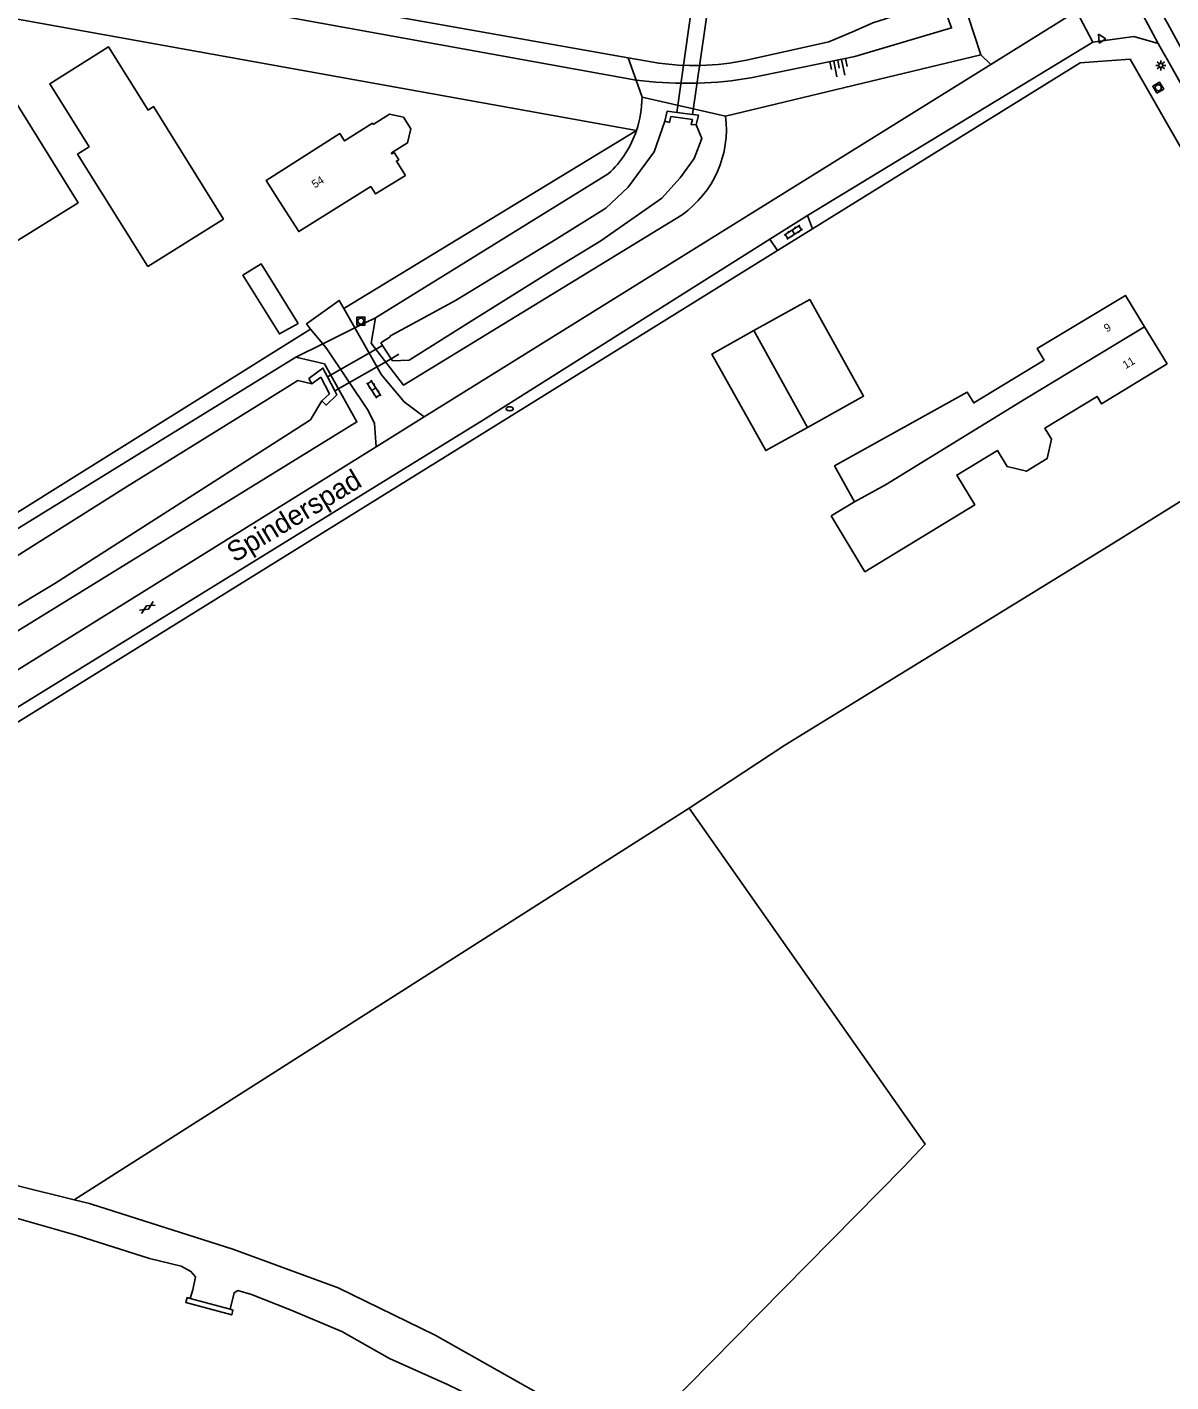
# Model space of a CAD drawing. Extents: x 133000 to 136000, y 400500 to 403500.
# Drawn here: x 133301.9 to 133444.8, y 401055.6 to 401224.9 of the extents above; entities that cross this region are included whole.
import ezdxf

# ---------------------------------------------------------------- set-up
doc = ezdxf.new("R2010")
doc.units = 0
for name, color, linetype in [('gg-afsc-draadraster', 7, 'Continuous'), ('gg-afsc-hekwerk', 7, 'Continuous'), ('gg-afsc-muur', 7, 'Continuous'), ('gg-anno-huisnummerreeks BGT', 7, 'Continuous'), ('gg-anno-openbare ruimte label', 7, 'Continuous'), ('gg-bbg-bijgebouw', 7, 'Continuous'), ('gg-bbg-hoofdgebouw', 7, 'Continuous'), ('gg-bbg-open loods', 7, 'Continuous'), ('gg-bbg-tussenscheiding', 7, 'Continuous'), ('gg-knt-BGT kruinlijn', 7, 'Continuous'), ('gg-knt-bovenkant onderkant talud', 7, 'Continuous'), ('gg-knt-verharding', 7, 'Continuous'), ('gg-kntw-bovenkant insteek waterloop', 7, 'Continuous'), ('gg-kntw-waterlijn', 7, 'Continuous'), ('gg-kwrk-duiker nz vlak', 7, 'Continuous'), ('gg-kwrk-faunavoorziening', 7, 'Continuous'), ('gg-kwrk-uitstroombak niveau min 01', 7, 'Continuous'), ('gt-grn-groengrens', 7, 'Continuous'), ('gt-grn-vlakafsluiter', 7, 'Continuous'), ('gt-symb-brandkraan', 7, 'Continuous'), ('gt-symb-gesloten verharding', 7, 'Continuous'), ('gt-symb-klinker verharding', 7, 'Continuous'), ('gt-symb-lichtmast', 7, 'Continuous'), ('gt-symb-rioolschacht', 7, 'Continuous'), ('gt-symb-talud symbool', 7, 'Continuous'), ('gt-symb-waterafsluiter', 7, 'Continuous'), ('gx-grn-maaiveld', 7, 'Continuous')]:
    doc.layers.add(name, color=color, linetype=linetype)

# ---------------------------------------------------------------- blocks, each defined once
blk = doc.blocks.new('gt0-RS')
at = {"layer": 'gt-symb-rioolschacht'}
blk.add_lwpolyline([(-0.5, -0.5), (0.5, -0.5), (0.5, 0.5), (-0.5, 0.5)], close=True, dxfattribs=at)
blk.add_circle((0, 0), 0.375, dxfattribs=at)
blk = doc.blocks.new('gt0-LMAST')
at = {"layer": 'gt-symb-lichtmast'}
for p, q in [((-0.18, 0.17), (-0.45, 0.44)), ((-0.01, 0.25), (-0.01, 0.62)), ((0.17, 0.17), (0.44, 0.44)), ((-0.26, 0), (-0.63, 0)), ((-0.18, -0.18), (-0.45, -0.45)), ((-0.01, -0.25), (-0.01, -0.63)), ((0.44, -0.45), (0.17, -0.18)), ((0.24, 0), (0.62, 0))]:
    blk.add_line(p, q, dxfattribs=at)
blk.add_circle((-0.01, 0), 0.25, dxfattribs=at)
blk = doc.blocks.new('gt0-WAFSL')
at = {"layer": 'gt-symb-waterafsluiter'}
for p, q in [((-0.5, -0.33), (0, 0.67)), ((0, 0.67), (0.5, -0.33)), ((0.5, -0.33), (-0.5, -0.33))]:
    blk.add_line(p, q, dxfattribs=at)
blk = doc.blocks.new('gt0-TALUD_1')
at = {"layer": 'gt-symb-talud symbool'}
for p, q in [((-1, -1), (-1, 0)), ((0.5, -2), (0.5, 0)), ((-0.5, -2), (-0.5, 0)), ((0, -1), (0, 0)), ((1, -1), (1, 0))]:
    blk.add_line(p, q, dxfattribs=at)
blk = doc.blocks.new('gt0-KL1')
at = {"layer": 'gt-symb-klinker verharding'}
for p, q in [((-1.15, 0.3), (1.15, 0.3)), ((-1, -0.3), (-1, 0.3)), ((-0.5, 0.3), (-0.5, 0.45)), ((0, -0.3), (0, 0.3)), ((0.5, 0.3), (0.5, 0.45)), ((1, -0.3), (1, 0.3)), ((-1.15, -0.3), (1.15, -0.3)), ((-0.5, -0.45), (-0.5, -0.3)), ((0.5, -0.45), (0.5, -0.3))]:
    blk.add_line(p, q, dxfattribs=at)
blk = doc.blocks.new('gt0-BR')
at = {"layer": 'gt-symb-brandkraan'}
for centre, radius, start, end in [((-0.24, 0), 0.206, 107.5669, 252.4331), ((0.6, -2.66), 3, 106.892, 107.5669), ((0, -0.69), 0.938, 73.108, 106.892), ((-0.6, -2.66), 3, 72.4331, 73.108), ((0.24, 0), 0.206, 287.567, 72.4331), ((0.6, 2.66), 3, 252.4331, 253.108), ((0, 0.69), 0.938, 253.108, 286.8921), ((-0.6, 2.66), 3, 286.8921, 287.567)]:
    blk.add_arc(centre, radius, start, end, dxfattribs=at)
blk = doc.blocks.new('gt0-GESVH1')
at = {"layer": 'gt-symb-gesloten verharding'}
for p, q in [((-0.99, -0.26), (0.01, 0.24)), ((0.01, -0.26), (-0.99, 0.24)), ((0.01, 0.24), (1.01, -0.26)), ((1.01, 0.24), (0.01, -0.26))]:
    blk.add_line(p, q, dxfattribs=at)

msp = doc.modelspace()

# ---------------------------------------------------------------- linework, layer by layer
at = {"layer": 'gg-afsc-draadraster'}
msp.add_lwpolyline([(133465.2, 401177.6), (133436.96, 401160.03), (133396.55, 401135.16), (133384.57, 401127.31)], dxfattribs=at)
at = {"layer": 'gg-afsc-hekwerk'}
msp.add_lwpolyline([(133435.08, 401220.54), (133439.67, 401220.88), (133459.11, 401186.98)], dxfattribs=at)
at = {"layer": 'gg-afsc-muur'}
msp.add_lwpolyline([(133348.29, 401184.03), (133347.35, 401183.43), (133346.27, 401185.12), (133346.07, 401185.44), (133347.24, 401186.2)], dxfattribs=at)
at = {"layer": 'gg-bbg-bijgebouw'}
for p, q in [((133326.41, 401200.9), (133316.94, 401194.99)), ((133399.38, 401174.88), (133392.67, 401186.97))]:
    msp.add_line(p, q, dxfattribs=at)
for points in [[(133316.94, 401194.99), (133308.17, 401209.03), (133309.61, 401209.93), (133304.69, 401217.82), (133312.04, 401222.41), (133316.97, 401214.52), (133317.66, 401214.95), (133326.41, 401200.9)], [(133289.72, 401215.25), (133297.55, 401220.13), (133308.26, 401202.94), (133300.42, 401198.06), (133289.72, 401215.25)], [(133335.71, 401187.85), (133333.39, 401186.55), (133328.83, 401193.89), (133331.1, 401195.3), (133335.71, 401187.85)], [(133392.67, 401186.97), (133387.43, 401184.04), (133394.15, 401171.98), (133399.38, 401174.88)]]:
    msp.add_lwpolyline(points, dxfattribs=at)
at = {"layer": 'gg-bbg-hoofdgebouw'}
for p, q in [((133441.47, 401187.46), (133444.31, 401182.8)), ((133402.31, 401163.81), (133405.24, 401165.56)), ((133406.55, 401156.82), (133402.31, 401163.81))]:
    msp.add_line(p, q, dxfattribs=at)
for points in [[(133345.1, 401212.73), (133347.12, 401213.99), (133348.88, 401213.62), (133349.79, 401212.17), (133349.4, 401210.42), (133347.38, 401209.16), (133347.45, 401209.05), (133347.72, 401209.22), (133348.29, 401208.32), (133348.01, 401208.15), (133349.13, 401206.36)], [(133345.1, 401212.73), (133345.01, 401212.88), (133341.53, 401210.66), (133340.95, 401211.58), (133331.74, 401205.71), (133333.39, 401203.12)], [(133349.13, 401206.36), (133345.4, 401204.04), (133344.82, 401204.97), (133335.8, 401199.34), (133333.39, 401203.12)], [(133428.95, 401183.29), (133428.08, 401184.75), (133439.09, 401191.37), (133441.47, 401187.46)], [(133405.24, 401165.56), (133402.74, 401170.07), (133419.33, 401179.27), (133420.14, 401177.94), (133428.95, 401183.29)], [(133444.31, 401182.8), (133436.11, 401177.81), (133435.54, 401178.75), (133429.02, 401174.79), (133429.87, 401173.39), (133429.3, 401170.98), (133426.71, 401169.41), (133424.31, 401170.01), (133423.1, 401172.01), (133418.01, 401168.93), (133420.27, 401165.21), (133406.55, 401156.82)]]:
    msp.add_lwpolyline(points, dxfattribs=at)
at = {"layer": 'gg-bbg-open loods'}
msp.add_lwpolyline([(133392.67, 401186.97), (133399.65, 401190.85), (133406.38, 401178.79), (133399.38, 401174.88)], dxfattribs=at)
at = {"layer": 'gg-bbg-tussenscheiding'}
msp.add_lwpolyline([(133405.24, 401165.56), (133409.13, 401167.72), (133426.52, 401178.39), (133441.47, 401187.46)], dxfattribs=at)
at = {"layer": 'gg-knt-BGT kruinlijn'}
msp.add_line((133209.8, 401248.76), (133377.94, 401218.24), dxfattribs=at)
for points in [[(133392.27, 401218.55), (133405.27, 401221.21), (133417.37, 401224.79), (133415.97, 401228.6)], [(133377.94, 401218.24), (133380.41, 401217.99), (133382.89, 401217.87), (133385.7, 401217.88)]]:
    msp.add_lwpolyline(points, dxfattribs=at)
msp.add_arc((133384.08, 401266.1), 48.25, 271.9242, 279.7732, dxfattribs=at)
at = {"layer": 'gg-knt-bovenkant onderkant talud'}
for p, q in [((133376.94, 401221.05), (133209.24, 401250.82)), ((133418.48, 401229.26), (133421.02, 401221.43)), ((133421.02, 401221.43), (133389.14, 401213.77))]:
    msp.add_line(p, q, dxfattribs=at)
for points in [[(133391.73, 401220.77), (133402.02, 401223.06), (133405.19, 401224.38), (133407.51, 401225.41), (133410.8, 401226.46), (133410.48, 401227.91)], [(133386.05, 401220.1), (133384.63, 401220.08), (133383.21, 401220.14), (133380.79, 401220.37), (133376.94, 401221.05)]]:
    msp.add_lwpolyline(points, dxfattribs=at)
msp.add_arc((133385.11, 401252.15), 32.07, 271.6661, 281.9033, dxfattribs=at)
at = {"layer": 'gg-knt-verharding'}
for p, q in [((133443.2, 401222.85), (133437.58, 401233.34)), ((133422.26, 401220.21), (133432.97, 401226.87)), ((133435.02, 401223.02), (133432.97, 401226.87)), ((133399.36, 401201.35), (133435.02, 401223.02)), ((133351.46, 401176.2), (133422.26, 401220.21)), ((133399.36, 401201.35), (133394.65, 401198.38)), ((133399.36, 401201.35), (133399.98, 401199.67)), ((133394.65, 401198.38), (133395.62, 401196.96)), ((133342.82, 401187.3), (133341.43, 401189.75)), ((133337.29, 401187.16), (133338.81, 401185.31)), ((133345.47, 401172.47), (133351.46, 401176.2)), ((133345.47, 401172.47), (133248.34, 401112.04))]:
    msp.add_line(p, q, dxfattribs=at)
for points in [[(133443.2, 401222.85), (133440.15, 401223.72), (133435.02, 401223.02)], [(133249.3, 401106.19), (133249.33, 401106.49), (133249.52, 401107.17), (133249.83, 401107.81), (133250.24, 401108.38), (133250.74, 401108.88), (133253.5, 401110.84), (133358.88, 401175.83), (133394.65, 401198.38)], [(133341.43, 401189.75), (133340.86, 401190.75), (133336.76, 401187.81), (133337.29, 401187.16)], [(133351.46, 401176.2), (133348.96, 401178.06), (133346.13, 401181.45), (133342.82, 401187.3)], [(133338.81, 401185.31), (133339.33, 401184.68), (133344.49, 401177.01), (133345.28, 401175.37), (133345.47, 401172.47)]]:
    msp.add_lwpolyline(points, dxfattribs=at)
for centre, radius, start, end in [((135147.9, 402169.75), 1947.82, 208.68031, 210.16323), ((134720.52, 401936.31), 1463.07, 209.18599, 210.66988)]:
    msp.add_arc(centre, radius, start, end, dxfattribs=at)
at = {"layer": 'gg-kntw-bovenkant insteek waterloop'}
for p, q in [((133378.69, 401216.13), (133389.14, 401213.77)), ((133345.38, 401188.56), (133374.48, 401206.55)), ((133229.22, 401118.21), (133335.42, 401183.64)), ((133307.74, 401078.39), (133309.67, 401077.91))]:
    msp.add_line(p, q, dxfattribs=at)
for points in [[(133383.7, 401201.45), (133348.88, 401180.17), (133344.84, 401185.41), (133345.38, 401188.56)], [(133230.94, 401106.47), (133343.06, 401175.57), (133339.01, 401182.84), (133335.42, 401183.64)], [(133281.23, 401085.11), (133286.95, 401083.77), (133300.72, 401080.13), (133307.74, 401078.39)], [(133322.23, 401066.06), (133322.55, 401067.13), (133322.9, 401068.76), (133322.33, 401069.44), (133321.13, 401070.07), (133317.15, 401071.05), (133308.11, 401073.94), (133296.7, 401077.15), (133286.6, 401079.39)], [(133309.67, 401077.91), (133309.92, 401077.85), (133327.58, 401072.2), (133340.72, 401067.37), (133352.84, 401061.49), (133365.76, 401054.18), (133376.45, 401047.36)], [(133374.15, 401044.89), (133371.35, 401046.58), (133362.09, 401051.58), (133354.38, 401055.3), (133347.15, 401058.56), (133341.19, 401061.91), (133334.65, 401064.69), (133329.91, 401066.57), (133328.17, 401067.04), (133327.73, 401066.77), (133327.25, 401064.7)]]:
    msp.add_lwpolyline(points, dxfattribs=at)
for centre, radius, start, end in [((133365.66, 401216.14), 13.03, 341.3667, 359.9459), ((133376.13, 401212.15), 13.11, 305.2702, 7.0925), ((133365.66, 401216.14), 13.03, 312.6063, 341.369)]:
    msp.add_arc(centre, radius, start, end, dxfattribs=at)
at = {"layer": 'gg-kntw-waterlijn'}
for points in [[(133347.19, 401186.28), (133355.39, 401190.72), (133367.96, 401198.38), (133374.17, 401202.26), (133376.98, 401204.91), (133380.21, 401209.31), (133381.53, 401213.13)], [(133347.5, 401183.19), (133349.58, 401183.26), (133356.99, 401187.95), (133368.01, 401194.83), (133373.56, 401198.17), (133381.18, 401203.51), (133383.46, 401206.07), (133385.19, 401208.49), (133386.15, 401210.98), (133385.44, 401212.69)], [(133346.27, 401185.12), (133346.07, 401185.44), (133347.24, 401186.2), (133347.19, 401186.28)], [(133227.28, 401113.16), (133230.29, 401114.69), (133234.67, 401117.41), (133265.87, 401136.76), (133301.86, 401159.63), (133314.29, 401167.45), (133331.81, 401178.31), (133335.7, 401180.72), (133337.43, 401180.32)], [(133229.28, 401109.51), (133233.81, 401111.99), (133244.29, 401118.7), (133305.32, 401155.37), (133337.25, 401175.82), (133338.7, 401178.21)]]:
    msp.add_lwpolyline(points, dxfattribs=at)
at = {"layer": 'gg-kwrk-duiker nz vlak'}
for p, q in [((133385.72, 401233.11), (133383.03, 401214.23)), ((133387.7, 401232.87), (133385.01, 401213.97)), ((133346.27, 401185.12), (133339.38, 401181.21)), ((133347.35, 401183.43), (133340.3, 401179.43))]:
    msp.add_line(p, q, dxfattribs=at)
at = {"layer": 'gg-kwrk-faunavoorziening'}
msp.add_line((133347.35, 401183.43), (133346.27, 401185.12), dxfattribs=at)
at = {"layer": 'gg-kwrk-uitstroombak niveau min 01'}
for p, q in [((133383.03, 401214.23), (133385.01, 401213.97)), ((133338.57, 401181.17), (133337.43, 401180.32)), ((133339.38, 401181.21), (133340.3, 401179.43)), ((133327.25, 401064.7), (133322.23, 401066.06))]:
    msp.add_line(p, q, dxfattribs=at)
for points in [[(133381.53, 401213.13), (133381.84, 401214.38), (133383.03, 401214.23)], [(133382.3, 401213.7), (133382.12, 401212.98), (133381.53, 401213.13)], [(133385.44, 401212.69), (133384.82, 401212.74), (133384.99, 401213.36), (133382.3, 401213.7)], [(133385.01, 401213.97), (133385.76, 401213.88), (133385.44, 401212.69)], [(133337.43, 401180.32), (133337.08, 401180.98), (133338.83, 401182.29), (133339.38, 401181.21)], [(133338.7, 401178.21), (133339.63, 401179.09), (133338.57, 401181.17)], [(133340.3, 401179.43), (133340.55, 401178.93), (133339.21, 401177.67), (133338.7, 401178.21)], [(133327.25, 401064.7), (133327.57, 401064.61), (133327.42, 401064.01), (133321.69, 401065.57), (133321.87, 401066.16), (133322.23, 401066.06)]]:
    msp.add_lwpolyline(points, dxfattribs=at)
at = {"layer": 'gt-grn-groengrens'}
for p, q in [((133376.94, 401221.05), (133377.94, 401218.24)), ((133422.26, 401220.21), (133421.02, 401221.43)), ((133377.94, 401218.24), (133378.69, 401216.13)), ((133341.43, 401189.75), (133378.01, 401211.98)), ((133249.3, 401106.19), (133395.62, 401196.96)), ((133342.82, 401187.3), (133345.38, 401188.56)), ((133335.42, 401183.64), (133338.81, 401185.31)), ((133384.57, 401127.31), (133307.74, 401078.39))]:
    msp.add_line(p, q, dxfattribs=at)
for points in [[(133212.32, 401241.8), (133217.29, 401240.91), (133378.01, 401211.98)], [(133399.98, 401199.67), (133433.43, 401220.42), (133435.08, 401220.54)], [(133337.29, 401187.16), (133230.61, 401120.5), (133225.87, 401168.98)], [(133377.68, 401048.42), (133378.38, 401049.02), (133411.37, 401082.47), (133414.08, 401085.35), (133384.57, 401127.31)]]:
    msp.add_lwpolyline(points, dxfattribs=at)
at = {"layer": 'gt-grn-vlakafsluiter'}
for p, q in [((133395.62, 401196.96), (133399.98, 401199.67)), ((133338.81, 401185.31), (133342.82, 401187.3))]:
    msp.add_line(p, q, dxfattribs=at)
at = {"layer": 'gx-grn-maaiveld'}
msp.add_line((133347.5, 401183.19), (133347.35, 401183.43), dxfattribs=at)

# ---------------------------------------------------------------- block references
at = {"layer": 'gt-symb-brandkraan'}
msp.add_blockref('gt0-BR', (133362.16, 401177.21), dxfattribs=at)
at = {"layer": 'gt-symb-gesloten verharding', "rotation": 31.671318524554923}
msp.add_blockref('gt0-GESVH1', (133316.88, 401152.38), dxfattribs=at)
at = {"layer": 'gt-symb-klinker verharding'}
for p, rotation in [((133397.6, 401199.28), 32.54589339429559), ((133345.19, 401179.64), -57.24756055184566)]:
    msp.add_blockref('gt0-KL1', p, dxfattribs=dict(at, rotation=rotation))
at = {"layer": 'gt-symb-lichtmast'}
msp.add_blockref('gt0-LMAST', (133443.52, 401220.11), dxfattribs=at)
at = {"layer": 'gt-symb-rioolschacht', "rotation": 31.13079914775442}
msp.add_blockref('gt0-RS', (133443.19, 401217.32), dxfattribs=at)
at = {"layer": 'gt-symb-rioolschacht'}
msp.add_blockref('gt0-RS', (133343.56, 401188.16), dxfattribs=at)
at = {"layer": 'gt-symb-talud symbool', "xscale": 1.0001999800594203, "yscale": 1.0001999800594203, "rotation": 11.534620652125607}
msp.add_blockref('gt0-TALUD_1', (133403.14, 401220.75), dxfattribs=at)
at = {"layer": 'gt-symb-waterafsluiter', "rotation": 31.003067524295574}
msp.add_blockref('gt0-WAFSL', (133436.05, 401223.44), dxfattribs=at)

# ---------------------------------------------------------------- texts
at = {"layer": 'gg-anno-huisnummerreeks BGT'}
for s, rotation, p in [('54', 32, (133337.81, 401204.72)), ('9', 31.3, (133436.78, 401186.73)), ('11', 31.3, (133439.12, 401182.14))]:
    msp.add_text(s, height=1, rotation=rotation, dxfattribs=at).set_placement(p)
at = {"layer": 'gg-anno-openbare ruimte label'}
msp.add_text('Spinderspad', height=2.5, rotation=31, dxfattribs=at).set_placement((133327.79, 401157.94))

doc.saveas('drawing.dxf')
